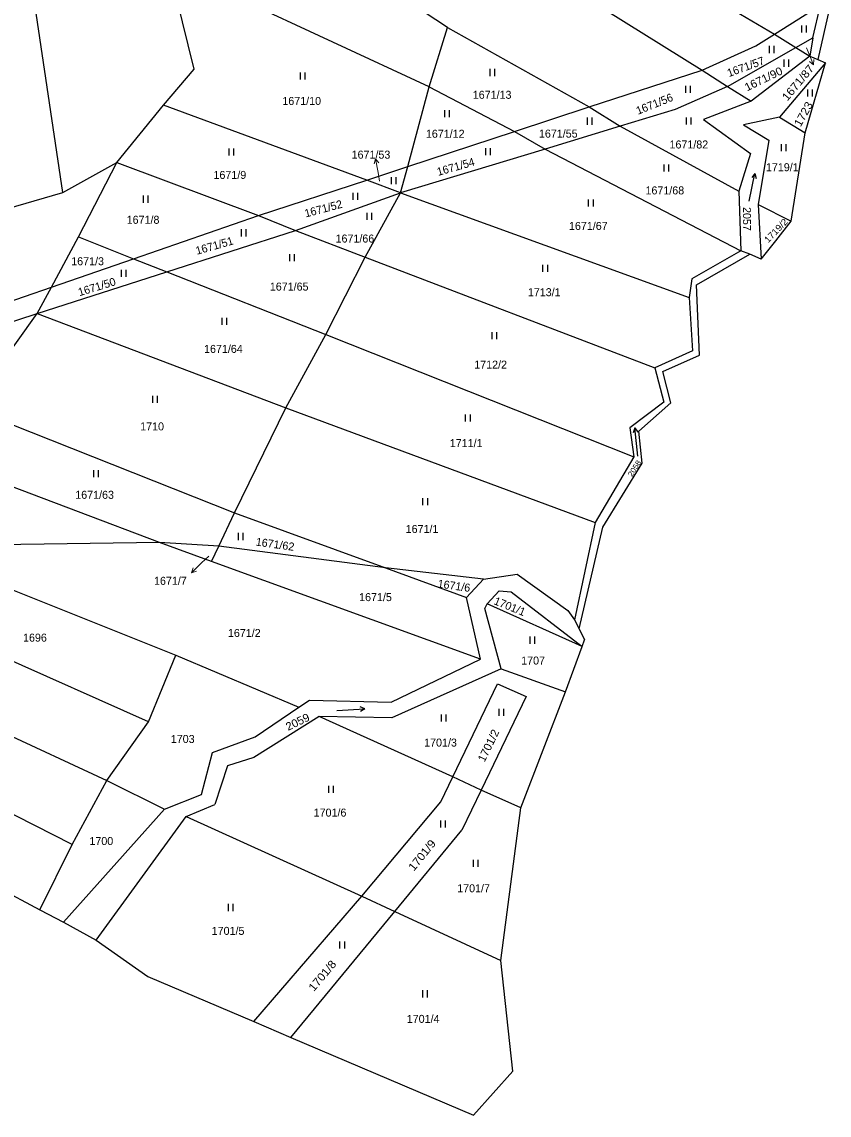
# Model space of a CAD drawing. Extents: x -820420 to -815896, y -1105820 to -1103643.
# Drawn here: x -818758.1 to -818586.7, y -1105819.8 to -1105587.5 of the extents above; entities that cross this region are included whole.
import ezdxf
from ezdxf.enums import TextEntityAlignment as Align

# ---------------------------------------------------------------- set-up
doc = ezdxf.new("R2010")
doc.units = 0
doc.header["$LTSCALE"] = 0.68
for name, color, linetype, lineweight in [('1', 7, 'Continuous', 25), ('3', 7, 'Continuous', 25), ('7', 7, 'Continuous', 13)]:
    doc.layers.add(name, color=color, linetype=linetype, lineweight=lineweight)
doc.layers.add('2', color=7, linetype='Continuous')

msp = doc.modelspace()

# ---------------------------------------------------------------- linework, layer by layer
at = {"layer": '1'}
for p, q in [((-818749.42, -1105623.81), (-818769.99, -1105484.32)), ((-818667.72, -1105588.74), (-818724.7, -1105550.9)), ((-818655.35, -1105556.4), (-818598.28, -1105590.14)), ((-818659.93, -1105568.85), (-818613.63, -1105597.78)), ((-818671.61, -1105601.32), (-818726.89, -1105575.65)), ((-818721.51, -1105597.54), (-818726.89, -1105575.65)), ((-818598.28, -1105590.14), (-818588.47, -1105583.97)), ((-818590.15, -1105590.89), (-818588.47, -1105583.97)), ((-818586.67, -1105584.86), (-818589.09, -1105595.52)), ((-818671.61, -1105601.32), (-818667.72, -1105588.74)), ((-818667.72, -1105588.74), (-818637.65, -1105605.56)), ((-818602.22, -1105592.62), (-818598.28, -1105590.14)), ((-818598.28, -1105590.14), (-818593.74, -1105592.94)), ((-818593.74, -1105592.94), (-818590.15, -1105590.89)), ((-818590.15, -1105590.89), (-818590.75, -1105594.79)), ((-818613.63, -1105597.78), (-818602.22, -1105592.62)), ((-818608.27, -1105601.23), (-818593.74, -1105592.94)), ((-818593.74, -1105592.94), (-818590.75, -1105594.79)), ((-818590.75, -1105594.79), (-818603.21, -1105604.34)), ((-818590.75, -1105594.79), (-818589.09, -1105595.52)), ((-818589.09, -1105595.52), (-818587.44, -1105596.25)), ((-818728.02, -1105605.23), (-818721.51, -1105597.54)), ((-818637.65, -1105605.56), (-818613.63, -1105597.78)), ((-818613.63, -1105597.78), (-818608.27, -1105601.23)), ((-818587.44, -1105596.25), (-818597.21, -1105607.77)), ((-818591.79, -1105611.09), (-818587.44, -1105596.25)), ((-818676.17, -1105618.28), (-818671.61, -1105601.32)), ((-818671.61, -1105601.32), (-818653.47, -1105610.84)), ((-818608.27, -1105601.23), (-818619.38, -1105606.15)), ((-818608.27, -1105601.23), (-818603.21, -1105604.34)), ((-818603.21, -1105604.34), (-818613.33, -1105608.26)), ((-818737.93, -1105617.42), (-818728.02, -1105605.23)), ((-818684.87, -1105621.13), (-818728.02, -1105605.23)), ((-818653.47, -1105610.84), (-818637.65, -1105605.56)), ((-818637.65, -1105605.56), (-818631.08, -1105609.71)), ((-818619.38, -1105606.15), (-818631.08, -1105609.71)), ((-818613.33, -1105608.26), (-818603.36, -1105615.46)), ((-818597.21, -1105607.77), (-818604.87, -1105609.41)), ((-818604.87, -1105609.41), (-818599.47, -1105612.64)), ((-818597.21, -1105607.77), (-818591.79, -1105611.09)), ((-818676.17, -1105618.28), (-818653.47, -1105610.84)), ((-818653.47, -1105610.84), (-818646.96, -1105614.54)), ((-818631.08, -1105609.71), (-818646.96, -1105614.54)), ((-818631.08, -1105609.71), (-818605.85, -1105623.51)), ((-818594.76, -1105629.89), (-818591.79, -1105611.09)), ((-818599.47, -1105612.64), (-818601.75, -1105626.3)), ((-818646.96, -1105614.54), (-818677.67, -1105623.84)), ((-818646.96, -1105614.54), (-818605.4, -1105636.18)), ((-818603.36, -1105615.46), (-818605.85, -1105623.51)), ((-818749.42, -1105623.81), (-818737.93, -1105617.42)), ((-818746.11, -1105633.23), (-818737.93, -1105617.42)), ((-818737.93, -1105617.42), (-818707.85, -1105628.66)), ((-818684.87, -1105621.13), (-818676.17, -1105618.28)), ((-818677.67, -1105623.84), (-818676.17, -1105618.28)), ((-818707.85, -1105628.66), (-818684.87, -1105621.13)), ((-818677.67, -1105623.84), (-818684.87, -1105621.13)), ((-818766.07, -1105628.64), (-818749.42, -1105623.81)), ((-818700.01, -1105631.86), (-818677.67, -1105623.84)), ((-818685.21, -1105637.54), (-818677.67, -1105623.84)), ((-818677.67, -1105623.84), (-818616.37, -1105646.1)), ((-818605.85, -1105623.51), (-818605.4, -1105636.18)), ((-818601.75, -1105626.3), (-818594.76, -1105629.89)), ((-818601.75, -1105626.3), (-818601.08, -1105637.97)), ((-818734.43, -1105637.85), (-818707.85, -1105628.66)), ((-818707.85, -1105628.66), (-818700.01, -1105631.86)), ((-818597.99, -1105634.02), (-818594.76, -1105629.89)), ((-818727.33, -1105640.65), (-818700.01, -1105631.86)), ((-818700.01, -1105631.86), (-818685.21, -1105637.54)), ((-818751.84, -1105643.87), (-818746.11, -1105633.23)), ((-818746.11, -1105633.23), (-818734.43, -1105637.85)), ((-818601.08, -1105637.97), (-818597.99, -1105634.02)), ((-818605.4, -1105636.18), (-818615.82, -1105642.11)), ((-818614.84, -1105643.4), (-818603.54, -1105636.9)), ((-818603.54, -1105636.9), (-818605.4, -1105636.18)), ((-818601.08, -1105637.97), (-818603.54, -1105636.9)), ((-818751.84, -1105643.87), (-818734.43, -1105637.85)), ((-818734.43, -1105637.85), (-818727.33, -1105640.65)), ((-818693.57, -1105653.98), (-818685.21, -1105637.54)), ((-818685.21, -1105637.54), (-818623.69, -1105661.06)), ((-818754.88, -1105649.51), (-818727.33, -1105640.65)), ((-818727.33, -1105640.65), (-818693.57, -1105653.98)), ((-818766.17, -1105648.82), (-818751.84, -1105643.87)), ((-818754.88, -1105649.51), (-818751.84, -1105643.87)), ((-818615.82, -1105642.11), (-818616.37, -1105646.1)), ((-818614.2, -1105658.36), (-818614.84, -1105643.4)), ((-818616.37, -1105646.1), (-818615.68, -1105657.43)), ((-818786.95, -1105659.82), (-818754.88, -1105649.51)), ((-818769.23, -1105669.54), (-818754.88, -1105649.51)), ((-818754.88, -1105649.51), (-818702.04, -1105669.52)), ((-818693.57, -1105653.98), (-818628.12, -1105679.93)), ((-818615.68, -1105657.43), (-818623.69, -1105661.06)), ((-818621.99, -1105661.8), (-818614.2, -1105658.36)), ((-818623.69, -1105661.06), (-818621.74, -1105668.34)), ((-818620.27, -1105668.5), (-818621.99, -1105661.8)), ((-818702.04, -1105669.52), (-818636.36, -1105693.91)), ((-818621.74, -1105668.34), (-818628.98, -1105673.77)), ((-818627.11, -1105674.47), (-818620.27, -1105668.5)), ((-818628.98, -1105673.77), (-818628.12, -1105679.93)), ((-818626.36, -1105681.26), (-818627.11, -1105674.47)), ((-818728.85, -1105698.12), (-818773.82, -1105681.11)), ((-818628.12, -1105679.93), (-818636.36, -1105693.91)), ((-818634.72, -1105694.87), (-818626.36, -1105681.26)), ((-818716.29, -1105698.96), (-818712.97, -1105691.83)), ((-818712.97, -1105691.83), (-818680.9, -1105703.56)), ((-818636.36, -1105693.91), (-818640.71, -1105714.59)), ((-818639.78, -1105716.53), (-818634.72, -1105694.87)), ((-818728.85, -1105698.12), (-818783.23, -1105698.96)), ((-818783.23, -1105698.96), (-818725.43, -1105722.12)), ((-818717.84, -1105702.22), (-818728.85, -1105698.12)), ((-818716.29, -1105698.96), (-818728.85, -1105698.12)), ((-818717.84, -1105702.22), (-818716.29, -1105698.96)), ((-818680.9, -1105703.56), (-818716.29, -1105698.96)), ((-818660.74, -1105722.95), (-818717.84, -1105702.22)), ((-818680.9, -1105703.56), (-818663.7, -1105709.85)), ((-818660.08, -1105705.92), (-818680.9, -1105703.56)), ((-818663.7, -1105709.85), (-818660.08, -1105705.92)), ((-818660.08, -1105705.92), (-818652.93, -1105704.87)), ((-818652.93, -1105704.87), (-818642.16, -1105712.62)), ((-818659.32, -1105711.19), (-818656.76, -1105708.45)), ((-818656.76, -1105708.45), (-818654.2, -1105708.64)), ((-818654.2, -1105708.64), (-818639.13, -1105720.27)), ((-818731.23, -1105736.23), (-818786.91, -1105711.43)), ((-818660.74, -1105722.95), (-818663.7, -1105709.85)), ((-818659.81, -1105712.17), (-818659.32, -1105711.19)), ((-818639.13, -1105720.27), (-818659.32, -1105711.19)), ((-818656.33, -1105724.96), (-818659.81, -1105712.17)), ((-818642.16, -1105712.62), (-818640.71, -1105714.59)), ((-818640.71, -1105714.59), (-818639.78, -1105716.53)), ((-818639.78, -1105716.53), (-818638.62, -1105718.82)), ((-818642.66, -1105729.9), (-818639.13, -1105720.27)), ((-818639.13, -1105720.27), (-818638.62, -1105718.82)), ((-818731.23, -1105736.23), (-818725.43, -1105722.12)), ((-818725.43, -1105722.12), (-818699.27, -1105733.14)), ((-818679.7, -1105732.09), (-818660.74, -1105722.95)), ((-818792.36, -1105724.6), (-818740.08, -1105748.69)), ((-818656.33, -1105724.96), (-818679.54, -1105735.43)), ((-818656.33, -1105724.96), (-818642.66, -1105729.9)), ((-818666.57, -1105747.95), (-818657.09, -1105728.18)), ((-818657.09, -1105728.18), (-818651.01, -1105730.87)), ((-818652.16, -1105754.55), (-818642.66, -1105729.9)), ((-818699.27, -1105733.14), (-818697.04, -1105731.64)), ((-818697.04, -1105731.64), (-818679.7, -1105732.09)), ((-818651.01, -1105730.87), (-818660.57, -1105750.76)), ((-818708.56, -1105739.41), (-818699.27, -1105733.14)), ((-818747.45, -1105762.29), (-818798.58, -1105736.34)), ((-818740.08, -1105748.69), (-818731.23, -1105736.23)), ((-818694.96, -1105735.11), (-818708.81, -1105743.82)), ((-818679.54, -1105735.43), (-818694.96, -1105735.11)), ((-818666.57, -1105747.95), (-818694.96, -1105735.11)), ((-818717.59, -1105742.77), (-818708.56, -1105739.41)), ((-818719.96, -1105751.72), (-818717.59, -1105742.77)), ((-818708.81, -1105743.82), (-818714.47, -1105745.58)), ((-818714.47, -1105745.58), (-818717.1, -1105753.81)), ((-818805.75, -1105748.63), (-818754.28, -1105776.22)), ((-818747.45, -1105762.29), (-818740.08, -1105748.69)), ((-818740.08, -1105748.69), (-818727.82, -1105754.84)), ((-818669.11, -1105753.24), (-818666.57, -1105747.95)), ((-818660.57, -1105750.76), (-818666.57, -1105747.95)), ((-818660.57, -1105750.76), (-818664.66, -1105759.27)), ((-818652.16, -1105754.55), (-818660.57, -1105750.76)), ((-818727.82, -1105754.84), (-818719.96, -1105751.72)), ((-818685.93, -1105773.31), (-818669.11, -1105753.24)), ((-818749.28, -1105778.83), (-818727.82, -1105754.84)), ((-818723.2, -1105756.39), (-818717.1, -1105753.81)), ((-818656.37, -1105787), (-818652.16, -1105754.55)), ((-818742.32, -1105782.64), (-818723.2, -1105756.39)), ((-818723.2, -1105756.39), (-818685.93, -1105773.31)), ((-818678.93, -1105776.58), (-818664.66, -1105759.27)), ((-818754.28, -1105776.22), (-818747.45, -1105762.29)), ((-818708.88, -1105799.93), (-818685.93, -1105773.31)), ((-818685.93, -1105773.31), (-818678.93, -1105776.58)), ((-818754.28, -1105776.22), (-818749.28, -1105778.83)), ((-818700.97, -1105803.3), (-818678.93, -1105776.58)), ((-818678.93, -1105776.58), (-818656.37, -1105787)), ((-818749.28, -1105778.83), (-818742.32, -1105782.64)), ((-818742.32, -1105782.64), (-818731.36, -1105790.34)), ((-818653.86, -1105810.52), (-818656.37, -1105787)), ((-818731.36, -1105790.34), (-818708.88, -1105799.93)), ((-818708.88, -1105799.93), (-818700.97, -1105803.3)), ((-818700.97, -1105803.3), (-818662.21, -1105819.83)), ((-818662.21, -1105819.83), (-818653.86, -1105810.52))]:
    msp.add_line(p, q, dxfattribs=at)
for points in [[(-818712.97, -1105691.83), (-818702.04, -1105669.52), (-818693.57, -1105653.98)], [(-818773.82, -1105681.11), (-818769.23, -1105669.54), (-818712.97, -1105691.83)]]:
    msp.add_lwpolyline(points, dxfattribs=at)
at = {"layer": '3'}
for p, q in [((-818592.441, -1105589.76), (-818592.441, -1105588.26)), ((-818591.44, -1105589.76), (-818591.44, -1105588.26)), ((-818599.331, -1105594.14), (-818599.331, -1105592.64)), ((-818598.33, -1105594.14), (-818598.33, -1105592.64)), ((-818596.251, -1105597.05), (-818596.251, -1105595.55)), ((-818595.25, -1105597.05), (-818595.25, -1105595.55)), ((-818658.631, -1105599.03), (-818658.631, -1105597.53)), ((-818657.63, -1105599.03), (-818657.63, -1105597.53)), ((-818698.951, -1105599.75), (-818698.951, -1105598.25)), ((-818697.95, -1105599.75), (-818697.95, -1105598.25)), ((-818617.081, -1105602.62), (-818617.081, -1105601.12)), ((-818616.08, -1105602.62), (-818616.08, -1105601.12)), ((-818591.211, -1105603.41), (-818591.211, -1105601.91)), ((-818590.21, -1105603.41), (-818590.21, -1105601.91)), ((-818668.291, -1105607.76), (-818668.291, -1105606.26)), ((-818667.29, -1105607.76), (-818667.29, -1105606.26)), ((-818637.971, -1105609.37), (-818637.971, -1105607.87)), ((-818636.97, -1105609.37), (-818636.97, -1105607.87)), ((-818616.971, -1105609.35), (-818616.971, -1105607.85)), ((-818615.97, -1105609.35), (-818615.97, -1105607.85)), ((-818596.811, -1105615.02), (-818596.811, -1105613.52)), ((-818595.81, -1105615.02), (-818595.81, -1105613.52)), ((-818714.101, -1105615.95), (-818714.101, -1105614.45)), ((-818713.1, -1105615.95), (-818713.1, -1105614.45)), ((-818659.561, -1105615.87), (-818659.561, -1105614.37)), ((-818658.56, -1105615.87), (-818658.56, -1105614.37)), ((-818621.721, -1105619.35), (-818621.721, -1105617.85)), ((-818620.72, -1105619.35), (-818620.72, -1105617.85)), ((-818679.621, -1105622.02), (-818679.621, -1105620.52)), ((-818678.62, -1105622.02), (-818678.62, -1105620.52)), ((-818602.424, -1105619.771), (-818602.137, -1105620.831)), ((-818732.281, -1105625.95), (-818732.281, -1105624.45)), ((-818731.28, -1105625.95), (-818731.28, -1105624.45)), ((-818687.761, -1105625.35), (-818687.761, -1105623.85)), ((-818686.76, -1105625.35), (-818686.76, -1105623.85)), ((-818637.741, -1105626.78), (-818637.741, -1105625.28)), ((-818636.74, -1105626.78), (-818636.74, -1105625.28)), ((-818684.761, -1105629.61), (-818684.761, -1105628.11)), ((-818683.76, -1105629.61), (-818683.76, -1105628.11)), ((-818711.451, -1105633.1), (-818711.451, -1105631.6)), ((-818710.45, -1105633.1), (-818710.45, -1105631.6)), ((-818701.221, -1105638.37), (-818701.221, -1105636.87)), ((-818700.22, -1105638.37), (-818700.22, -1105636.87)), ((-818647.441, -1105640.63), (-818647.441, -1105639.13)), ((-818646.44, -1105640.63), (-818646.44, -1105639.13)), ((-818736.981, -1105641.71), (-818736.981, -1105640.21)), ((-818735.98, -1105641.71), (-818735.98, -1105640.21)), ((-818715.601, -1105651.91), (-818715.601, -1105650.41)), ((-818714.6, -1105651.91), (-818714.6, -1105650.41)), ((-818658.231, -1105654.95), (-818658.231, -1105653.45)), ((-818657.23, -1105654.95), (-818657.23, -1105653.45)), ((-818730.321, -1105668.49), (-818730.321, -1105666.99)), ((-818729.32, -1105668.49), (-818729.32, -1105666.99)), ((-818663.861, -1105672.45), (-818663.861, -1105670.95)), ((-818662.86, -1105672.45), (-818662.86, -1105670.95)), ((-818627.907, -1105673.808), (-818627.306, -1105674.728)), ((-818742.811, -1105684.28), (-818742.811, -1105682.78)), ((-818741.81, -1105684.28), (-818741.81, -1105682.78)), ((-818672.921, -1105690.22), (-818672.921, -1105688.72)), ((-818671.92, -1105690.22), (-818671.92, -1105688.72)), ((-818712.101, -1105697.62), (-818712.101, -1105696.12)), ((-818711.1, -1105697.62), (-818711.1, -1105696.12)), ((-818650.171, -1105719.65), (-818650.171, -1105718.15)), ((-818649.17, -1105719.65), (-818649.17, -1105718.15)), ((-818685.237, -1105733.501), (-818686.186, -1105734.053)), ((-818669.001, -1105736.2), (-818669.001, -1105734.7)), ((-818668, -1105736.2), (-818668, -1105734.7)), ((-818656.741, -1105735.01), (-818656.741, -1105733.51)), ((-818655.74, -1105735.01), (-818655.74, -1105733.51)), ((-818692.931, -1105751.33), (-818692.931, -1105749.83)), ((-818691.93, -1105751.33), (-818691.93, -1105749.83)), ((-818669.121, -1105758.71), (-818669.121, -1105757.21)), ((-818668.12, -1105758.71), (-818668.12, -1105757.21)), ((-818662.211, -1105767.05), (-818662.211, -1105765.55)), ((-818661.21, -1105767.05), (-818661.21, -1105765.55)), ((-818714.241, -1105776.46), (-818714.241, -1105774.96)), ((-818713.24, -1105776.46), (-818713.24, -1105774.96)), ((-818690.551, -1105784.44), (-818690.551, -1105782.94)), ((-818689.55, -1105784.44), (-818689.55, -1105782.94)), ((-818672.931, -1105794.8), (-818672.931, -1105793.3)), ((-818671.93, -1105794.8), (-818671.93, -1105793.3))]:
    msp.add_line(p, q, dxfattribs=at)
for points in [[(-818603.672, -1105625.639), (-818602.424, -1105619.771), (-818603.118, -1105620.622)], [(-818627.28, -1105679.776), (-818627.907, -1105673.808), (-818628.303, -1105674.833)], [(-818691.228, -1105733.815), (-818685.237, -1105733.501), (-818686.239, -1105733.051)]]:
    msp.add_lwpolyline(points, dxfattribs=at)
at = {"layer": '7'}
for p, q in [((-818590.016, -1105596.652), (-818589.927, -1105595.536)), ((-818682.971, -1105616.605), (-818683.29, -1105617.678)), ((-818722.089, -1105704.585), (-818721.02, -1105704.249))]:
    msp.add_line(p, q, dxfattribs=at)
for points in [[(-818591.48, -1105593.07), (-818591.14, -1105593.87), (-818590.016, -1105596.652), (-818590.855, -1105595.912)], [(-818682.14, -1105621.39), (-818682.45, -1105619.56), (-818682.971, -1105616.605), (-818682.304, -1105617.504)], [(-818718.4, -1105701.02), (-818719.93, -1105702.5), (-818722.089, -1105704.585), (-818721.716, -1105703.529)]]:
    msp.add_lwpolyline(points, dxfattribs=at)

# ---------------------------------------------------------------- texts
at = {"layer": '2'}
for s, rotation, p in [('1671/57', 20, (-818604.0962, -1105597.8549)), ('1671/56', 22, (-818623.4484, -1105605.7378)), ('1671/54', 16, (-818665.7428, -1105619.1236)), ('1671/52', 15, (-818693.848, -1105628.0297)), ('2057', 270, (-818604.965, -1105629.399)), ('1671/51', 16, (-818716.9828, -1105635.8936)), ('1671/50', 17, (-818741.9385, -1105644.6275)), ('1671/62', 352, (-818704.4378, -1105699.3586)), ('1671/6', 352, (-818666.4478, -1105708.1789)), ('1701/1', 338, (-818654.7969, -1105712.519))]:
    msp.add_text(s, height=1.7, rotation=rotation, dxfattribs=at).set_placement(p, align=Align.CENTER)
for s, height, rotation, width, p in [('1671/90', 1.7, 26, 1.05, (-818600.2236, -1105600.4188)), ('1671/87', 1.7, 50, 1.1, (-818592.6305, -1105600.9949)), ('1723', 1.7, 61, 1.1, (-818591.3814, -1105607.5261)), ('1719/2', 1.386, 46, 1.1, (-818597.4531, -1105632.3649)), ('2058', 1.14, 57, 1.1, (-818627.5275, -1105682.7069)), ('2059', 1.7, 26, 1.05, (-818699.1736, -1105737.0294)), ('1701/2', 1.7, 64, 1.05, (-818658.2549, -1105741.6756)), ('1701/9', 1.7, 51, 1.1, (-818672.4591, -1105765.1349)), ('1701/8', 1.7, 50, 1.1, (-818693.6404, -1105790.7444))]:
    msp.add_text(s, height=height, rotation=rotation, dxfattribs=dict(at, width=width)).set_placement(p, align=Align.CENTER)
for s, p in [('1671/13', (-818658.239, -1105603.865)), ('1671/10', (-818698.679, -1105605.175)), ('1671/12', (-818668.199, -1105612.145)), ('1671/55', (-818644.189, -1105612.115)), ('1671/82', (-818616.459, -1105614.425)), ('1719/1', (-818596.61, -1105619.255)), ('1671/9', (-818713.94, -1105620.895)), ('1671/68', (-818621.559, -1105624.185)), ('1671/8', (-818732.37, -1105630.425)), ('1671/67', (-818637.809, -1105631.735)), ('1671/66', (-818687.379, -1105634.415)), ('1671/3', (-818744.15, -1105639.235)), ('1671/65', (-818701.339, -1105644.625)), ('1713/1', (-818647.17, -1105645.815)), ('1671/64', (-818715.309, -1105657.865)), ('1712/2', (-818658.56, -1105661.205)), ('1710', (-818730.45, -1105674.325)), ('1711/1', (-818663.76, -1105677.885)), ('1671/63', (-818742.659, -1105688.865)), ('1671/1', (-818673.12, -1105696.125)), ('1671/5', (-818683.01, -1105710.605)), ('1696', (-818755.33, -1105719.215)), ('1671/2', (-818710.87, -1105718.225)), ('1707', (-818649.54, -1105724.085)), ('1703', (-818723.95, -1105740.745)), ('1701/3', (-818669.2, -1105741.515)), ('1701/6', (-818692.66, -1105756.395)), ('1700', (-818741.23, -1105762.435)), ('1701/7', (-818662.18, -1105772.475)), ('1701/5', (-818714.32, -1105781.525)), ('1701/4', (-818672.89, -1105800.225))]:
    msp.add_text(s, height=1.7, dxfattribs=at).set_placement(p, align=Align.CENTER)
for s, p in [('1671/53', (-818679.86, -1105616.585)), ('1671/7', (-818723.089, -1105707.145))]:
    msp.add_text(s, height=1.7, dxfattribs=at).set_placement(p, align=Align.RIGHT)

doc.saveas('drawing.dxf')
